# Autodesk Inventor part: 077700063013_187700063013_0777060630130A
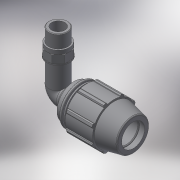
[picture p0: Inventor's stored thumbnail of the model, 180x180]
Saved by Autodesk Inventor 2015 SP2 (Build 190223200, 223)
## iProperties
Created: 2017-02
Part Number: 077700063013_187700063013_0777060630130A
Material: Generic
Description: PLASSON 90° ELBOW MALE WITH INTEGRAL BRASS THREAD 63-1.1/4"
Document SubType Name: Modeling
Designer: KIM
Mass: 174.249 g
Surface Area: 431.906 cm^2
Volume: 174.249 cm^3
Density: 1 g/cm^3
Appearance: Default
Author: KIM
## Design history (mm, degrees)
derived "07770.ipt"
feature "Solid1::07770.ipt"
tag "TaggingFeature1"
body "Solid1"
other parameters: "d2" = 63, "d4" = 14, "d5" = 42, "d7" = 113, "d9" = 24, "d11" = 5.6, "d13" = 120 deg, "d14" = 81.9, "d15" = 12 deg, "d16" = 98.31, "d18" = 3.15, "d19" = 35 deg, "d20" = 17.5 deg, "d21" = 105.09, "d23" = 0, "d25" = 360 deg, "d27" = 2.26, "d33" = 1.26, "d42" = 62.16, "d43" = 3.39, "d46" = 1.89, "d51" = 168, "d68" = 11.2, "d72" = 126, "d73" = 41.91, "d74" = 22, "d75" = 48.1965, "d76" = 29.337, "d79" = 16.764, "d80" = 1.2573, "d83" = 0, "d84" = 0, "d91" = 84.75, "d94" = 41.91, "d95" = 29.337, "d96" = 11.2, "d97" = 50 deg, "d98" = 2.8, "d99" = 95.3607, "d100" = 2.8, "d101" = 2.8, "d105" = 2.2, "d106" = 50.292, "d107" = 22, "d108" = 13.2, "d109" = 0, "d_" = 63, "E_" = 113, "A_" = 168, "l_2" = 22, "A_1" = 126, "R_" = 41.91
